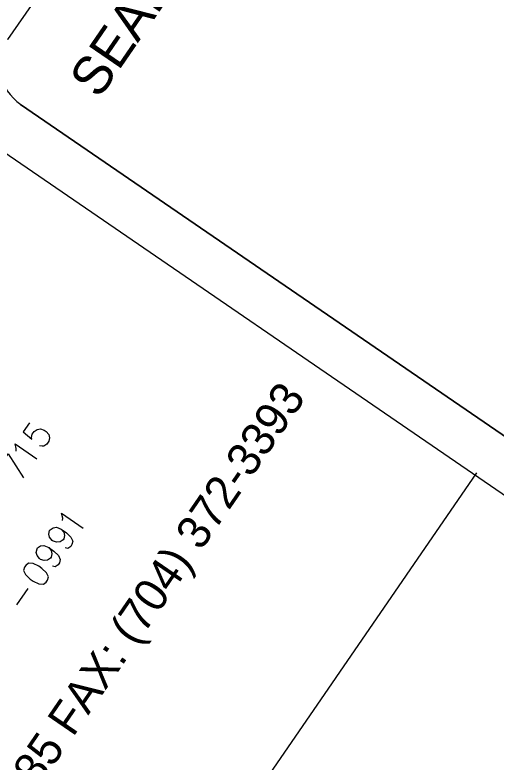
# Model space of a CAD drawing. Extents: x 1638787 to 1643250, y 391480 to 396306.
# Drawn here: x 1642326.7 to 1642512.5, y 394029.8 to 394318.6 of the extents above; entities that cross this region are included whole.
import ezdxf

# ---------------------------------------------------------------- set-up
doc = ezdxf.new("R2010")
doc.units = 0
doc.layers.add('Old_Level_60', color=7, linetype='Continuous')
doc.layers.add('UC Title Plan Sheet 34 CELL', color=7, linetype='Continuous')

msp = doc.modelspace()

# ---------------------------------------------------------------- linework, layer by layer
at = {"layer": 'Old_Level_60'}
msp.add_line((1642327.4, 394090.52), (1642331.77, 394096.88), dxfattribs=at)
for points in [[(1642332.27, 394160.97), (1642329.85, 394157.43), (1642333.21, 394154.61), (1642333.05, 394155.24), (1642333.38, 394156.57), (1642334.11, 394157.63), (1642335.24, 394158.42), (1642336.52, 394158.58), (1642337.97, 394158.11), (1642338.77, 394157.56), (1642339.73, 394156.38), (1642340.04, 394155.12), (1642339.72, 394153.79), (1642338.99, 394152.73), (1642337.86, 394151.94), (1642337.22, 394151.86), (1642336.17, 394152.06)], [(1642327.09, 394149.97), (1642327.17, 394150.96), (1642326.7, 394152.84), (1642335.11, 394147.07)], [(1642320.64, 394144), (1642324.03, 394148.95), (1642330.02, 394139.65)], [(1642345.04, 394123.11), (1642345.13, 394124.09), (1642344.65, 394125.98), (1642353.07, 394120.21)], [(1642344.55, 394119.81), (1642345.51, 394118.64), (1642345.82, 394117.38), (1642345.5, 394116.04), (1642345.26, 394115.69), (1642344.13, 394114.9), (1642342.84, 394114.75), (1642341.4, 394115.22), (1642341, 394115.49), (1642340.04, 394116.67), (1642339.72, 394117.93), (1642340.05, 394119.26), (1642340.29, 394119.62), (1642341.42, 394120.4), (1642342.7, 394120.56), (1642344.55, 394119.81), (1642346.55, 394118.44), (1642348.31, 394116.71), (1642349.03, 394115.18), (1642348.7, 394113.85), (1642348.22, 394113.14), (1642347.09, 394112.35), (1642346.05, 394112.55)], [(1642339.7, 394112.74), (1642340.66, 394111.57), (1642340.98, 394110.31), (1642340.65, 394108.98), (1642340.41, 394108.62), (1642339.28, 394107.84), (1642337.99, 394107.68), (1642336.55, 394108.15), (1642336.15, 394108.42), (1642335.19, 394109.6), (1642334.87, 394110.86), (1642335.2, 394112.19), (1642335.44, 394112.55), (1642336.57, 394113.33), (1642337.86, 394113.49), (1642339.7, 394112.74), (1642341.7, 394111.37), (1642343.46, 394109.64), (1642344.18, 394108.11), (1642343.86, 394106.78), (1642343.37, 394106.07), (1642342.24, 394105.28), (1642341.2, 394105.48)], [(1642330.35, 394105.12), (1642330.03, 394103.79), (1642330.74, 394102.26), (1642332.5, 394100.53), (1642333.71, 394099.71), (1642335.95, 394098.69), (1642337.64, 394098.57), (1642338.77, 394099.36), (1642339.25, 394100.06), (1642339.58, 394101.4), (1642338.86, 394102.93), (1642337.1, 394104.65), (1642335.9, 394105.48), (1642333.65, 394106.5), (1642331.97, 394106.62), (1642330.84, 394105.83), (1642330.35, 394105.12)]]:
    msp.add_lwpolyline(points, dxfattribs=at)
at = {"layer": 'UC Title Plan Sheet 34 CELL'}
for p, q in [((1642323.93, 394309.21), (1642459.69, 394506.97)), ((1642328.85, 394284.08), (1642609.89, 394091.25)), ((1642609.89, 394091.25), (1642328.85, 394284.08)), ((1642328.85, 394284.08), (1642609.89, 394091.25)), ((1642600.57, 394074.7), (1642319.52, 394267.5)), ((1642160.08, 393639.31), (1642505.16, 394141.59))]:
    msp.add_line(p, q, dxfattribs=at)
msp.add_ellipse((1642339.09, 394298.71), major_axis=(-15.61, 10.71), ratio=0.941469, start_param=6.283006, end_param=7.85338, dxfattribs=at)

# ---------------------------------------------------------------- texts
for s, height, p in [('SEAL ', 14.836, (1642359.14, 394285.82)), ('(704) 372-1885 FAX: (704) 372-3393', 12.7764, (1642280.28, 393938.86)), ('PROJECT DESIGN ENGINEER', 14.8358, (1642387.25, 393797.19))]:
    msp.add_text(s, height=height, rotation=55.5455, dxfattribs=at).set_placement(p)

doc.saveas('drawing.dxf')
